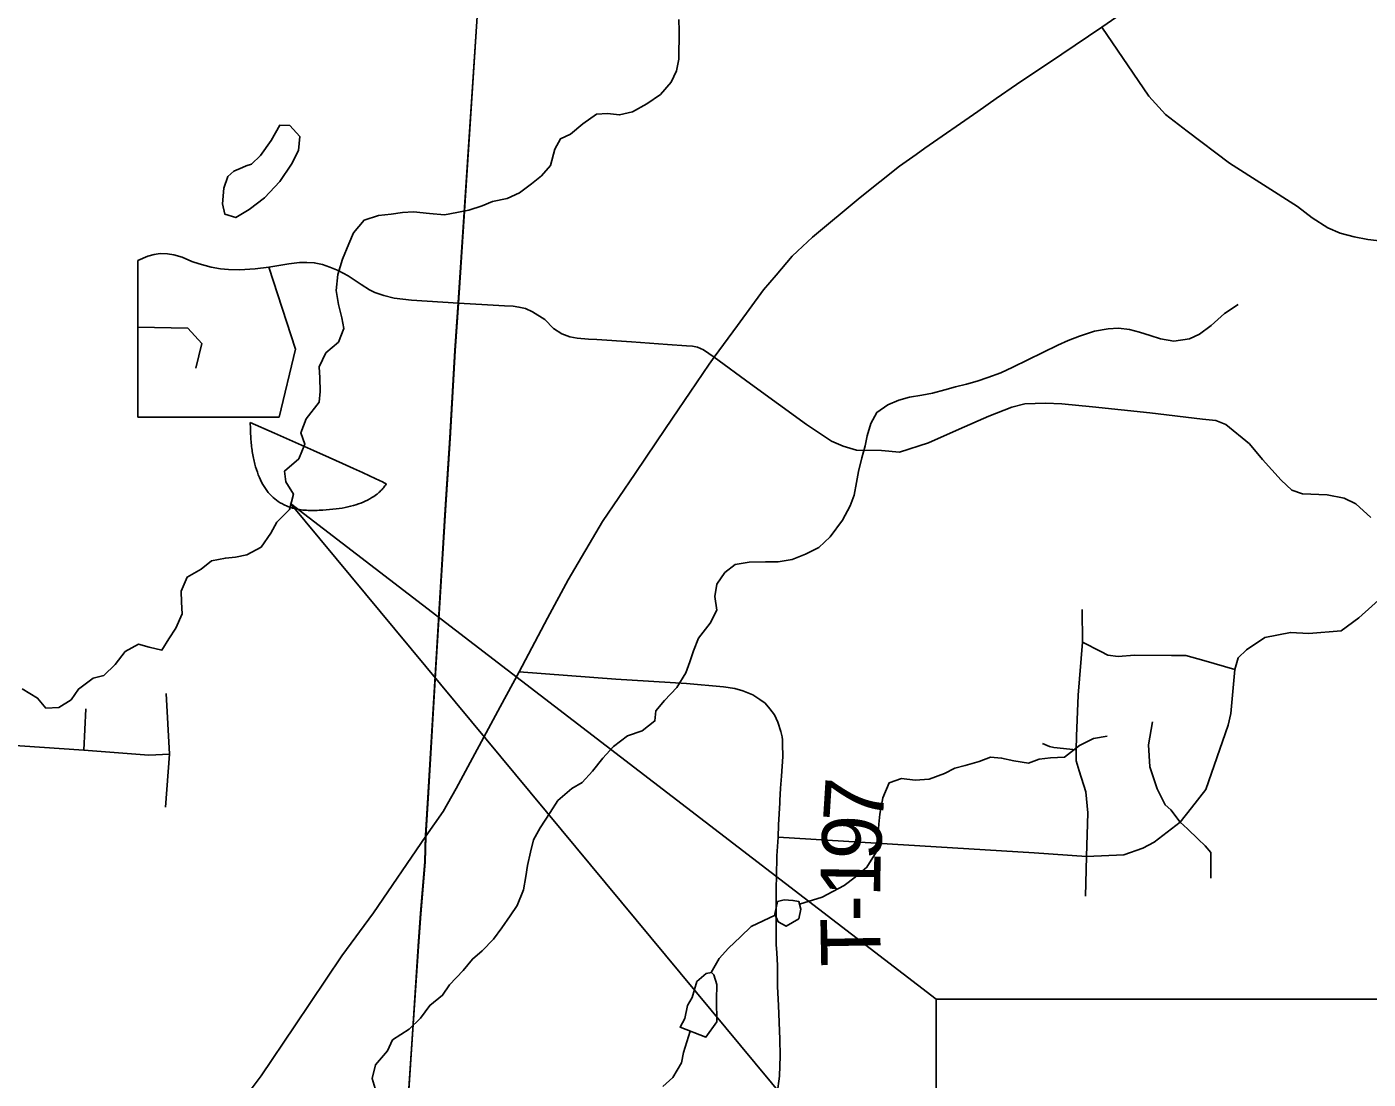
# Model space of a CAD drawing. Extents: x 208586767.6 to 208586821.4, y -134301046.9 to -134301022.9.
# Drawn here: x 208586780.239 to 208586781.515, y -134301028.455 to -134301027.454 of the extents above; entities that cross this region are included whole.
import ezdxf

# ---------------------------------------------------------------- set-up
doc = ezdxf.new("R2010")
doc.units = 0
for name, color, linetype in [('GM_X_City_Street', 7, 'Continuous'), ('GM_X_Corporation', 7, 'Continuous'), ('GM_X_Minor_Lake', 7, 'Continuous'), ('GM_X_Minor_River', 7, 'Continuous'), ('GM_X_Township_Road', 7, 'Continuous'), ('GM_X_Township_Road_Text', 7, 'Continuous'), ('GM_X_US_Route', 7, 'Continuous'), ('SH_Data', 7, 'Continuous'), ('SH_Text', 7, 'Continuous')]:
    doc.layers.add(name, color=color, linetype=linetype)

msp = doc.modelspace()

# ---------------------------------------------------------------- linework, layer by layer
at = {"layer": 'GM_X_City_Street'}
for p, q in [((208586780.3443, -134301027.6762), (208586780.3443, -134301027.8254)), ((208586780.4942, -134301027.7607), (208586780.4687, -134301027.6824)), ((208586780.3443, -134301027.7395), (208586780.3917, -134301027.7407)), ((208586780.3917, -134301027.7407), (208586780.4051, -134301027.7552)), ((208586780.4051, -134301027.7552), (208586780.3995, -134301027.7786)), ((208586780.4786, -134301027.8254), (208586780.4942, -134301027.7607)), ((208586780.3443, -134301027.8254), (208586780.4786, -134301027.8254)), ((208586780.2928, -134301028.1423), (208586780.2946, -134301028.1029))]:
    msp.add_line(p, q, dxfattribs=at)
for points in [[(208586780.6279, -134301028.0637), (208586780.6369, -134301027.9137), (208586780.6413, -134301027.8456), (208586780.6462, -134301027.7622), (208586780.6492, -134301027.7167), (208586780.6666, -134301027.4534)], [(208586781.5313, -134301027.658), (208586781.5147, -134301027.6561), (208586781.5015, -134301027.6538), (208586781.4883, -134301027.6502), (208586781.4765, -134301027.645), (208586781.4616, -134301027.6356), (208586781.4477, -134301027.6248), (208586781.3831, -134301027.5837), (208586781.3426, -134301027.5531), (208586781.322, -134301027.5371), (208586781.3062, -134301027.5197), (208586781.2616, -134301027.4542)], [(208586780.3443, -134301027.6762), (208586780.3536, -134301027.672), (208586780.3598, -134301027.6704), (208586780.3655, -134301027.6696), (208586780.3724, -134301027.6698), (208586780.3783, -134301027.6708), (208586780.3865, -134301027.6731), (208586780.3955, -134301027.6771), (208586780.4025, -134301027.6793), (208586780.4141, -134301027.6825), (208586780.4228, -134301027.6841), (208586780.4305, -134301027.6847), (208586780.4409, -134301027.6851), (208586780.4559, -134301027.684), (208586780.4687, -134301027.6824), (208586780.488, -134301027.6793), (208586780.4979, -134301027.6782), (208586780.505, -134301027.678), (208586780.512, -134301027.6784), (208586780.5198, -134301027.68), (208586780.5268, -134301027.6824), (208586780.5347, -134301027.6858), (208586780.5442, -134301027.6909), (208586780.5566, -134301027.6989), (208586780.5646, -134301027.704), (208586780.5698, -134301027.7067), (208586780.5783, -134301027.7096), (208586780.588, -134301027.712), (208586780.6045, -134301027.7139), (208586780.6492, -134301027.7167)], [(208586780.6492, -134301027.7167), (208586780.6768, -134301027.7183), (208586780.6932, -134301027.7194), (208586780.7012, -134301027.7198), (208586780.7069, -134301027.7205), (208586780.7131, -134301027.722), (208586780.7196, -134301027.725), (208586780.7314, -134301027.7323), (208586780.7398, -134301027.7409), (208586780.7478, -134301027.7461), (208586780.7553, -134301027.7489), (208586780.7624, -134301027.75), (208586780.773, -134301027.7509), (208586780.781, -134301027.7513), (208586780.8138, -134301027.7537), (208586780.8482, -134301027.756), (208586780.8664, -134301027.7574), (208586780.8719, -134301027.7578), (208586780.8768, -134301027.7588), (208586780.8824, -134301027.7613), (208586780.8925, -134301027.7682)], [(208586780.8925, -134301027.7682), (208586780.9272, -134301027.7934), (208586780.9804, -134301027.8324), (208586781.0042, -134301027.8481), (208586781.0155, -134301027.853), (208586781.0282, -134301027.8566), (208586781.0517, -134301027.8569), (208586781.069, -134301027.8585), (208586781.0967, -134301027.8496), (208586781.1257, -134301027.8366), (208586781.1541, -134301027.8242), (208586781.176, -134301027.8159), (208586781.1884, -134301027.8127), (208586781.2078, -134301027.812), (208586781.2234, -134301027.8127), (208586781.2525, -134301027.8153), (208586781.3071, -134301027.8212), (208586781.3573, -134301027.8273), (208586781.37, -134301027.8283), (208586781.3794, -134301027.8321), (208586781.4019, -134301027.8505), (208586781.4144, -134301027.8657), (208586781.4322, -134301027.8851), (208586781.4422, -134301027.8947), (208586781.4525, -134301027.8983), (208586781.4758, -134301027.8991), (208586781.492, -134301027.9025), (208586781.5032, -134301027.9077), (208586781.5174, -134301027.9208)], [(208586780.9535, -134301028.2249), (208586781.1971, -134301028.24), (208586781.247, -134301028.2434), (208586781.2824, -134301028.2419), (208586781.3005, -134301028.2356), (208586781.3112, -134301028.2297), (208586781.3361, -134301028.2107), (208586781.3468, -134301028.197), (208586781.3605, -134301028.1795), (208586781.3819, -134301028.1185), (208586781.3844, -134301028.1073), (208586781.388, -134301028.0653), (208586781.3913, -134301028.0542), (208586781.3991, -134301028.0466), (208586781.4165, -134301028.0349), (208586781.441, -134301028.0302), (208586781.4584, -134301028.0313), (208586781.4894, -134301028.0287), (208586781.5061, -134301028.0164), (208586781.534, -134301027.9913)], [(208586781.2459, -134301028.281), (208586781.247, -134301028.2434), (208586781.2483, -134301028.2019), (208586781.2464, -134301028.1819), (208586781.24, -134301028.1619), (208586781.2371, -134301028.1522), (208586781.2372, -134301028.1418), (208586781.2375, -134301028.1288), (208586781.239, -134301028.0897), (208586781.2431, -134301028.0395), (208586781.2429, -134301028.0083)], [(208586781.2431, -134301028.0395), (208586781.2605, -134301028.0483), (208586781.2673, -134301028.0517), (208586781.2771, -134301028.0531), (208586781.2927, -134301028.0517), (208586781.3278, -134301028.0522), (208586781.3414, -134301028.0522), (208586781.3585, -134301028.057), (208586781.388, -134301028.0653)], [(208586780.6182, -134301028.2241), (208586780.6208, -134301028.1827), (208586780.6279, -134301028.0637)], [(208586780.0155, -134301028.0905), (208586780.1024, -134301028.0965), (208586780.1259, -134301028.0982), (208586780.1341, -134301028.0996), (208586780.1406, -134301028.1026), (208586780.1484, -134301028.1071), (208586780.1734, -134301028.1257), (208586780.183, -134301028.1314), (208586780.1917, -134301028.1349), (208586780.1988, -134301028.1361), (208586780.2128, -134301028.1367), (208586780.2928, -134301028.1423), (208586780.3547, -134301028.147), (208586780.3744, -134301028.1461)], [(208586780.3704, -134301028.1964), (208586780.3744, -134301028.1461), (208586780.3713, -134301028.0884)], [(208586781.3429, -134301028.2171), (208586781.3361, -134301028.2107), (208586781.3273, -134301028.199), (208586781.3219, -134301028.1941), (208586781.3141, -134301028.179), (208586781.3073, -134301028.158), (208586781.3058, -134301028.137), (208586781.3097, -134301028.1151)], [(208586781.2051, -134301028.1359), (208586781.2117, -134301028.1388), (208586781.216, -134301028.1397), (208586781.2372, -134301028.1418)], [(208586781.3653, -134301028.2639), (208586781.3653, -134301028.2395), (208586781.36, -134301028.2331), (208586781.3532, -134301028.2268), (208586781.3429, -134301028.2171)], [(208586780.5626, -134301029.1848), (208586780.5611, -134301029.1724), (208586780.5599, -134301029.1589), (208586780.5602, -134301029.1485), (208586780.5596, -134301029.1333), (208586780.563, -134301029.0526), (208586780.5681, -134301028.9817), (208586780.5725, -134301028.9155), (208586780.5788, -134301028.8144), (208586780.606, -134301028.408), (208586780.6115, -134301028.3243), (208586780.6135, -134301028.2978), (208586780.6176, -134301028.2488), (208586780.6182, -134301028.2241)]]:
    msp.add_lwpolyline(points, dxfattribs=at)
at = {"layer": 'GM_X_Corporation'}
for points in [[(208586780.5786, -134301028.8139), (208586780.6058, -134301028.4074), (208586780.6113, -134301028.3238), (208586780.6133, -134301028.2973), (208586780.6174, -134301028.2483), (208586780.6179, -134301028.2235), (208586780.6206, -134301028.1821), (208586780.6366, -134301027.9132), (208586780.6411, -134301027.845), (208586780.646, -134301027.7617), (208586780.649, -134301027.7162), (208586780.6781, -134301027.2766), (208586780.6889, -134301027.0521), (208586780.3847, -134301027.0352), (208586780.023, -134301027.0133), (208586779.8905, -134301027.0043), (208586779.8313, -134301027.0004), (208586779.719, -134301026.9925), (208586779.4919, -134301026.9779), (208586779.278, -134301026.9613), (208586778.8851, -134301026.9328)], [(208586781.6677, -134301027.1118), (208586781.2713, -134301027.0897), (208586781.2244, -134301027.0871), (208586781.2193, -134301027.0875), (208586780.8223, -134301027.0634), (208586780.7721, -134301027.0589), (208586780.6889, -134301027.0521), (208586780.6781, -134301027.2766), (208586780.649, -134301027.7162), (208586780.646, -134301027.7617), (208586780.6411, -134301027.845), (208586780.6366, -134301027.9132), (208586780.6206, -134301028.1821), (208586780.6179, -134301028.2235), (208586780.6174, -134301028.2483), (208586780.6133, -134301028.2973), (208586780.6113, -134301028.3238), (208586780.6058, -134301028.4074), (208586780.5786, -134301028.8139)]]:
    msp.add_lwpolyline(points, dxfattribs=at)
at = {"layer": 'GM_X_Minor_Lake'}
for points in [[(208586780.4356, -134301027.5913), (208586780.4299, -134301027.5962), (208586780.426, -134301027.6075), (208586780.4248, -134301027.6223), (208586780.427, -134301027.6322), (208586780.4373, -134301027.6353), (208586780.4502, -134301027.6278), (208586780.4647, -134301027.6165), (208586780.4792, -134301027.601), (208586780.4903, -134301027.5844), (208586780.4972, -134301027.5715), (208586780.4985, -134301027.5582), (208586780.4887, -134301027.5476), (208586780.4792, -134301027.5475), (208586780.4711, -134301027.5619), (208586780.4608, -134301027.5762), (208586780.4524, -134301027.5845)], [(208586780.4524, -134301027.5845), (208586780.4473, -134301027.5861), (208586780.4437, -134301027.5878), (208586780.4356, -134301027.5913)], [(208586780.9504, -134301028.2983), (208586780.9534, -134301028.3055), (208586780.961, -134301028.3097), (208586780.9731, -134301028.3026), (208586780.9751, -134301028.2935), (208586780.9732, -134301028.2863), (208586780.9676, -134301028.2851), (208586780.9592, -134301028.2847), (208586780.9528, -134301028.2863)], [(208586780.9528, -134301028.2863), (208586780.9504, -134301028.2983)], [(208586780.8851, -134301028.3548), (208586780.876, -134301028.3624), (208586780.8717, -134301028.3775), (208586780.8671, -134301028.3851), (208586780.8648, -134301028.3976), (208586780.8602, -134301028.4059), (208586780.8848, -134301028.4152), (208586780.8951, -134301028.4008), (208586780.8949, -134301028.3799), (208586780.8953, -134301028.3651), (208586780.8924, -134301028.356)], [(208586780.8924, -134301028.356), (208586780.89, -134301028.3537), (208586780.8851, -134301028.3548)]]:
    msp.add_lwpolyline(points, dxfattribs=at)
at = {"layer": 'GM_X_Minor_River'}
for points in [[(208586780.6593, -134301027.6283), (208586780.6719, -134301027.6242), (208586780.6818, -134301027.6201), (208586780.6958, -134301027.6171), (208586780.7073, -134301027.6119), (208586780.7187, -134301027.6032), (208586780.7282, -134301027.5957), (208586780.737, -134301027.5858), (208586780.7409, -134301027.5703), (208586780.7463, -134301027.5605), (208586780.7558, -134301027.556), (208586780.7676, -134301027.5462), (208586780.7806, -134301027.5368), (208586780.7912, -134301027.5364), (208586780.8026, -134301027.5377), (208586780.8148, -134301027.5347), (208586780.8285, -134301027.5272), (208586780.8414, -134301027.5181), (208586780.8518, -134301027.5064), (208586780.8568, -134301027.4958), (208586780.8591, -134301027.4845), (208586780.8593, -134301027.4575), (208586780.859, -134301027.4469)], [(208586780.2341, -134301028.0838), (208586780.2488, -134301028.0926), (208586780.2567, -134301028.1022), (208586780.2689, -134301028.1015), (208586780.2807, -134301028.0943), (208586780.2876, -134301028.0841), (208586780.3017, -134301028.0736), (208586780.3119, -134301028.071), (208586780.3226, -134301028.0608), (208586780.3322, -134301028.0483), (208586780.3448, -134301028.0412), (208586780.355, -134301028.0443), (208586780.3671, -134301028.047), (208586780.3736, -134301028.0361), (208586780.3805, -134301028.0262), (208586780.3863, -134301028.0126), (208586780.3856, -134301028.0012), (208586780.3853, -134301027.991), (208586780.3911, -134301027.9774), (208586780.4044, -134301027.9698), (208586780.4143, -134301027.9619), (208586780.4276, -134301027.9594), (208586780.4371, -134301027.9586), (208586780.4478, -134301027.9564), (208586780.4615, -134301027.9489), (208586780.4707, -134301027.9357), (208586780.4764, -134301027.9251), (208586780.4886, -134301027.913), (208586780.4922, -134301027.8986), (208586780.485, -134301027.8868), (208586780.4839, -134301027.8766), (208586780.4973, -134301027.8649), (208586780.5031, -134301027.8509), (208586780.4994, -134301027.8402), (208586780.5044, -134301027.827), (208586780.5166, -134301027.8111), (208586780.5178, -134301027.8009), (208586780.5175, -134301027.788), (208586780.5168, -134301027.7773), (208586780.523, -134301027.7641), (208586780.5352, -134301027.7539), (208586780.5402, -134301027.741), (208586780.5384, -134301027.7308), (208586780.535, -134301027.7179), (208586780.5328, -134301027.7046), (208586780.5345, -134301027.6894), (208586780.5391, -134301027.675), (208586780.5449, -134301027.6602), (208586780.5495, -134301027.65), (208586780.5595, -134301027.6379), (208586780.5731, -134301027.6335), (208586780.5853, -134301027.632), (208586780.5959, -134301027.6306), (208586780.6066, -134301027.6299), (208586780.6217, -134301027.6315), (208586780.6361, -134301027.6327), (208586780.6479, -134301027.6305), (208586780.6593, -134301027.6283)], [(208586781.2674, -134301027.7412), (208586781.2773, -134301027.7405), (208586781.2879, -134301027.7417), (208586781.2974, -134301027.7444), (208586781.3076, -134301027.7475), (208586781.3174, -134301027.7506), (208586781.3299, -134301027.7529), (208586781.3448, -134301027.7507), (208586781.3546, -134301027.7462), (208586781.3657, -134301027.7379), (208586781.3783, -134301027.7266), (208586781.3913, -134301027.718)], [(208586780.571, -134301028.4672), (208586780.5672, -134301028.4546), (208586780.5704, -134301028.4418), (208586780.5818, -134301028.4282), (208586780.5864, -134301028.418), (208586780.6024, -134301028.4078), (208586780.6131, -134301028.3972), (208586780.6219, -134301028.3851), (208586780.6342, -134301028.3754), (208586780.6407, -134301028.3655), (208586780.6537, -134301028.3519), (208586780.6625, -134301028.341), (208586780.672, -134301028.3331), (208586780.6827, -134301028.3221), (208586780.6907, -134301028.3112), (208586780.6984, -134301028.2998), (208586780.7053, -134301028.29), (208586780.7111, -134301028.2752), (208586780.7134, -134301028.2624), (208586780.715, -134301028.2521), (208586780.7177, -134301028.2392), (208586780.7208, -134301028.2275), (208586780.727, -134301028.2161), (208586780.7366, -134301028.2014), (208586780.7439, -134301028.1901), (208586780.7572, -134301028.1787), (208586780.7671, -134301028.1731), (208586780.777, -134301028.1622), (208586780.7866, -134301028.1497), (208586780.7969, -134301028.1388), (208586780.8103, -134301028.1286), (208586780.824, -134301028.1237), (208586780.8362, -134301028.1143), (208586780.837, -134301028.1048), (208586780.8454, -134301028.095), (208586780.8572, -134301028.0826), (208586780.8657, -134301028.0686), (208586780.8695, -134301028.058), (208586780.873, -134301028.0477), (208586780.8777, -134301028.0356), (208586780.8888, -134301028.0213), (208586780.8953, -134301028.0088), (208586780.8931, -134301027.9959), (208586780.8951, -134301027.9841), (208586780.9027, -134301027.9732), (208586780.9126, -134301027.9656), (208586780.9259, -134301027.9634), (208586780.9415, -134301027.9628), (208586780.9536, -134301027.9628), (208586780.9669, -134301027.9606), (208586780.9795, -134301027.9558), (208586780.9921, -134301027.9494), (208586781.0031, -134301027.9392), (208586781.0146, -134301027.9233), (208586781.0219, -134301027.9097), (208586781.0258, -134301027.8995), (208586781.0281, -134301027.8874), (208586781.0301, -134301027.8771), (208586781.0332, -134301027.8639), (208586781.0363, -134301027.8525), (208586781.0383, -134301027.843), (208586781.0418, -134301027.8313), (208586781.0475, -134301027.8207), (208586781.0578, -134301027.8135), (208586781.0685, -134301027.8091), (208586781.0784, -134301027.8061), (208586781.0901, -134301027.8043), (208586781.1004, -134301027.8024), (208586781.1122, -134301027.7994), (208586781.1224, -134301027.7965), (208586781.1327, -134301027.7939), (208586781.143, -134301027.7909), (208586781.1532, -134301027.7875), (208586781.1654, -134301027.7831), (208586781.1768, -134301027.7778), (208586781.2195, -134301027.7568), (208586781.2294, -134301027.7523), (208586781.2404, -134301027.7482), (208586781.2545, -134301027.7434), (208586781.2674, -134301027.7412)], [(208586780.9739, -134301028.2888), (208586780.9953, -134301028.2822), (208586781.0056, -134301028.2766), (208586781.0162, -134301028.271), (208586781.0269, -134301028.2631), (208586781.038, -134301028.2536), (208586781.0468, -134301028.2393), (208586781.0484, -134301028.226), (208586781.0492, -134301028.2127), (208586781.0504, -134301028.2032), (208586781.0532, -134301028.1877), (208586781.059, -134301028.1733), (208586781.0708, -134301028.1692), (208586781.084, -134301028.1708), (208586781.0973, -134301028.1697), (208586781.1118, -134301028.1645), (208586781.1217, -134301028.1593), (208586781.1316, -134301028.1567), (208586781.1449, -134301028.153), (208586781.1555, -134301028.1488), (208586781.1661, -134301028.1497), (208586781.1779, -134301028.1524), (208586781.1919, -134301028.1547), (208586781.2018, -134301028.1506), (208586781.2128, -134301028.1496), (208586781.2261, -134301028.1489), (208586781.2402, -134301028.1376), (208586781.2536, -134301028.1312), (208586781.2665, -134301028.129)], [(208586780.8897, -134301028.3538), (208586780.8974, -134301028.3405), (208586780.9062, -134301028.3307), (208586780.9176, -134301028.3197), (208586780.9279, -134301028.3099), (208586780.9508, -134301028.2992)], [(208586780.8439, -134301028.4624), (208586780.8534, -134301028.4537), (208586780.8615, -134301028.4397), (208586780.8634, -134301028.4298), (208586780.8698, -134301028.4095)]]:
    msp.add_lwpolyline(points, dxfattribs=at)
at = {"layer": 'GM_X_Township_Road'}
for p, q in [((208586780.9559, -134301028.1784), (208586780.9567, -134301028.1668)), ((208586780.9552, -134301028.19), (208586780.9559, -134301028.1784))]:
    msp.add_line(p, q, dxfattribs=at)
for points in [[(208586780.9575, -134301028.1324), (208586780.9573, -134301028.1294), (208586780.9562, -134301028.1243), (208586780.9533, -134301028.1155), (208586780.9499, -134301028.1086), (208586780.9457, -134301028.103), (208586780.941, -134301028.0976), (208586780.9362, -134301028.0939), (208586780.9293, -134301028.0895), (208586780.9199, -134301028.0858), (208586780.9123, -134301028.0835), (208586780.9015, -134301028.0818), (208586780.8662, -134301028.0788), (208586780.799, -134301028.0746), (208586780.7071, -134301028.0677)], [(208586780.9567, -134301028.1668), (208586780.9579, -134301028.1482), (208586780.9577, -134301028.1366), (208586780.9575, -134301028.1324)], [(208586780.954, -134301028.2133), (208586780.955, -134301028.1923), (208586780.9552, -134301028.19)], [(208586780.9522, -134301028.2449), (208586780.9522, -134301028.2429), (208586780.9535, -134301028.2249), (208586780.954, -134301028.2133)], [(208586780.9521, -134301028.3352), (208586780.9517, -134301028.3272), (208586780.9515, -134301028.2753), (208586780.9522, -134301028.2449)], [(208586780.9537, -134301028.3852), (208586780.9529, -134301028.3672), (208586780.9528, -134301028.3472), (208586780.9521, -134301028.3352)], [(208586780.8885, -134301028.9854), (208586780.8963, -134301028.8566), (208586780.8998, -134301028.8403), (208586780.9034, -134301028.8284), (208586780.9089, -134301028.8156), (208586780.917, -134301028.7987), (208586780.9207, -134301028.7883), (208586780.9224, -134301028.7781), (208586780.9318, -134301028.634), (208586780.9359, -134301028.5898), (208586780.9474, -134301028.5056), (208586780.9526, -134301028.469), (208586780.9548, -134301028.4523), (208586780.9553, -134301028.433), (208586780.9552, -134301028.4172), (208586780.9537, -134301028.3852)]]:
    msp.add_lwpolyline(points, dxfattribs=at)
at = {"layer": 'GM_X_US_Route'}
for points in [[(208586781.1998, -134301027.4956), (208586781.2108, -134301027.4883), (208586781.2616, -134301027.4542), (208586781.2851, -134301027.438)], [(208586781.1611, -134301027.5221), (208586781.1804, -134301027.5087), (208586781.1998, -134301027.4956)], [(208586780.972, -134301027.6673), (208586780.9862, -134301027.6541), (208586781.0316, -134301027.6162), (208586781.0689, -134301027.5863), (208586781.0849, -134301027.5752), (208586781.0932, -134301027.5694), (208586781.1435, -134301027.5344), (208586781.1611, -134301027.5221)], [(208586780.9516, -134301027.6901), (208586780.9667, -134301027.6721), (208586780.972, -134301027.6673)], [(208586780.7071, -134301028.0677), (208586780.734, -134301028.0167), (208586780.7537, -134301027.9801), (208586780.7865, -134301027.9245), (208586780.8176, -134301027.879), (208586780.8379, -134301027.8487), (208586780.8531, -134301027.8263), (208586780.8699, -134301027.8015), (208586780.8878, -134301027.7749), (208586780.8925, -134301027.7682), (208586780.9149, -134301027.7379), (208586780.9397, -134301027.7042), (208586780.9516, -134301027.6901)], [(208586780.0761, -134301028.7938), (208586780.0947, -134301028.7847), (208586780.1507, -134301028.7743), (208586780.1765, -134301028.7704), (208586780.2261, -134301028.7606), (208586780.2459, -134301028.7542), (208586780.2642, -134301028.7445), (208586780.2808, -134301028.7318), (208586780.3045, -134301028.6973), (208586780.3298, -134301028.6365), (208586780.3408, -134301028.6128), (208586780.3909, -134301028.5476), (208586780.4198, -134301028.5079), (208586780.4615, -134301028.452), (208586780.4935, -134301028.4044), (208586780.5382, -134301028.3379), (208586780.5685, -134301028.297), (208586780.6182, -134301028.2241), (208586780.6346, -134301028.2006), (208586780.6472, -134301028.1786), (208586780.6891, -134301028.1008), (208586780.7071, -134301028.0677)]]:
    msp.add_lwpolyline(points, dxfattribs=at)
at = {"layer": 'SH_Data'}
msp.add_open_spline([(208586780.4512, -134301027.8304), (208586780.4512, -134301027.914), (208586780.566, -134301027.914), (208586780.5816, -134301027.8873)], degree=2, dxfattribs=at)
at = {"layer": 'SH_Text'}
for points in [[(208586781.104, -134301028.379), (208586781.104, -134301028.6474), (208586780.4895, -134301027.9075)], [(208586781.104, -134301028.379), (208586783.373, -134301028.379), (208586783.373, -134301028.9519), (208586781.104, -134301028.9519)]]:
    msp.add_lwpolyline(points, close=True, dxfattribs=at)

# ---------------------------------------------------------------- texts
at = {"layer": 'GM_X_Township_Road_Text'}
for s, rotation, p in [('7', 86.3496, (208586781.0528, -134301028.2129)), ('9', 87.1313, (208586781.051, -134301028.2477)), ('1', 89.0737, (208586781.0505, -134301028.2822)), ('-', 90.0234, (208586781.0505, -134301028.3053)), ('T', 91.0372, (208586781.0513, -134301028.3475))]:
    msp.add_text(s, height=0.0568, rotation=rotation, dxfattribs=at).set_placement(p)

doc.saveas('drawing.dxf')
